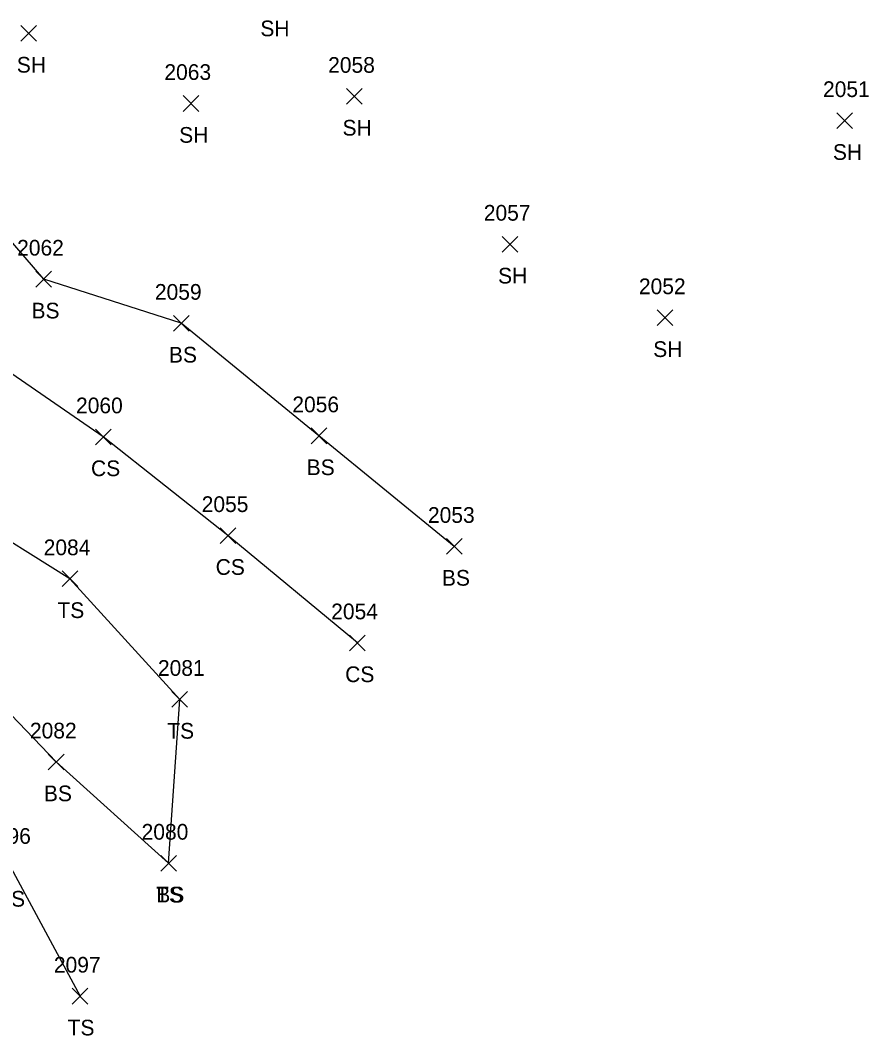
# Model space of a CAD drawing. Extents: x 1520648 to 1523413, y 732854 to 735518.
# Drawn here: x 1522132.5 to 1522240.5, y 733592.7 to 733722 of the extents above; entities that cross this region are included whole.
import ezdxf

# ---------------------------------------------------------------- set-up
doc = ezdxf.new("R2010")
doc.units = 0
for name, color, linetype in [('L_A', 7, 'Continuous'), ('L_I', 7, 'Continuous'), ('L_TIC', 7, 'Continuous'), ('LELB', 7, 'Continuous')]:
    doc.layers.add(name, color=color, linetype=linetype)

msp = doc.modelspace()

# ---------------------------------------------------------------- linework, layer by layer
at = {"layer": 'L_TIC'}
for points in [[(1522132.59, 733719.29), (1522134.59, 733721.29)], [(1522134.59, 733719.29), (1522132.59, 733721.29)], [(1522174.06, 733711.27), (1522176.06, 733713.27)], [(1522176.06, 733711.27), (1522174.06, 733713.27)], [(1522153.26, 733710.36), (1522155.26, 733712.36)], [(1522155.26, 733710.36), (1522153.26, 733712.36)], [(1522236.5, 733708.18), (1522238.5, 733710.18)], [(1522238.5, 733708.18), (1522236.5, 733710.18)], [(1522193.87, 733692.44), (1522195.87, 733694.44)], [(1522195.87, 733692.44), (1522193.87, 733694.44)], [(1522134.51, 733687.99), (1522136.51, 733689.99)], [(1522136.51, 733687.99), (1522134.51, 733689.99)], [(1522213.62, 733683.08), (1522215.62, 733685.08)], [(1522215.62, 733683.08), (1522213.62, 733685.08)], [(1522152.01, 733682.37), (1522154.01, 733684.37)], [(1522154.01, 733682.37), (1522152.01, 733684.37)], [(1522142.09, 733667.91), (1522144.09, 733669.91)], [(1522144.09, 733667.91), (1522142.09, 733669.91)], [(1522169.55, 733668.04), (1522171.55, 733670.04)], [(1522171.55, 733668.04), (1522169.55, 733670.04)], [(1522157.96, 733655.34), (1522159.96, 733657.34)], [(1522159.96, 733655.34), (1522157.96, 733657.34)], [(1522186.77, 733653.96), (1522188.77, 733655.96)], [(1522188.77, 733653.96), (1522186.77, 733655.96)], [(1522137.84, 733649.84), (1522139.84, 733651.84)], [(1522139.84, 733649.84), (1522137.84, 733651.84)], [(1522174.45, 733641.68), (1522176.45, 733643.68)], [(1522176.45, 733641.68), (1522174.45, 733643.68)], [(1522151.83, 733634.48), (1522153.83, 733636.48)], [(1522153.83, 733634.48), (1522151.83, 733636.48)], [(1522136.09, 733626.51), (1522138.09, 733628.51)], [(1522138.09, 733626.51), (1522136.09, 733628.51)], [(1522150.4, 733613.62), (1522152.4, 733615.62)], [(1522152.4, 733613.62), (1522150.4, 733615.62)], [(1522150.4, 733613.62), (1522152.4, 733615.62)], [(1522152.4, 733613.62), (1522150.4, 733615.62)], [(1522139.14, 733596.69), (1522141.14, 733598.69)], [(1522141.14, 733596.69), (1522139.14, 733598.69)]]:
    msp.add_lwpolyline(points, dxfattribs=at)
at = {"layer": 'LELB'}
for points in [[(1522175.45, 733642.68), (1522158.96, 733656.34), (1522143.09, 733668.91), (1522126.49, 733680.32), (1522112.21, 733698.89), (1522093.01, 733716.82), (1522086.71, 733701.67), (1522076.07, 733682.31), (1522062.1, 733669.53), (1522040.49, 733638.5)], [(1522187.77, 733654.96), (1522170.55, 733669.04), (1522153.01, 733683.37), (1522135.51, 733688.99), (1522119.92, 733707.07)], [(1522151.4, 733614.62), (1522152.83, 733635.48), (1522138.84, 733650.84), (1522125.94, 733658.88), (1522109.84, 733673.94), (1522100.92, 733684.14), (1522090.71, 733694.57), (1522087.23, 733686.84), (1522071.15, 733667.54), (1522069.93, 733665.76), (1522040.49, 733638.5)], [(1522151.4, 733614.62), (1522137.09, 733627.51), (1522120.8, 733644.52), (1522115.51, 733655.32), (1522103.6, 733667.72), (1522087.23, 733686.84)], [(1522071.15, 733667.54), (1522091.55, 733646.72), (1522109.98, 733629.81), (1522131.31, 733614.09), (1522140.14, 733597.69)]]:
    msp.add_lwpolyline(points, dxfattribs=at)

# ---------------------------------------------------------------- texts
at = {"layer": 'L_A'}
for s, p in [('SH', (1522163.09, 733719.92)), ('SH', (1522132.08, 733715.29)), ('SH', (1522152.75, 733706.36)), ('SH', (1522173.55, 733707.27)), ('SH', (1522235.99, 733704.18)), ('SH', (1522193.36, 733688.44)), ('BS', (1522133.95, 733683.99)), ('SH', (1522213.11, 733679.08)), ('BS', (1522151.45, 733678.37)), ('CS', (1522141.53, 733663.91)), ('BS', (1522168.99, 733664.04)), ('CS', (1522157.4, 733651.34)), ('BS', (1522186.21, 733649.96)), ('TS', (1522137.25, 733645.84)), ('CS', (1522173.89, 733637.68)), ('TS', (1522151.24, 733630.48)), ('BS', (1522135.53, 733622.51)), ('TS', (1522129.72, 733609.09)), ('TS', (1522149.81, 733609.62)), ('BS', (1522149.84, 733609.62)), ('TS', (1522138.55, 733592.69))]:
    msp.add_text(s, height=2, dxfattribs=at).set_placement(p)
at = {"layer": 'L_I'}
for s, p in [('2058', (1522171.72, 733715.27)), ('2063', (1522150.87, 733714.36)), ('2051', (1522234.73, 733712.18)), ('2057', (1522191.54, 733696.44)), ('2062', (1522132.12, 733691.99)), ('2052', (1522211.29, 733687.08)), ('2059', (1522149.66, 733686.37)), ('2060', (1522139.62, 733671.91)), ('2056', (1522167.16, 733672.04)), ('2055', (1522155.62, 733659.34)), ('2053', (1522184.43, 733657.96)), ('2084', (1522135.5, 733653.84)), ('2054', (1522172.11, 733645.68)), ('2081', (1522150.05, 733638.48)), ('2082', (1522133.75, 733630.51)), ('2096', (1522127.92, 733617.09)), ('2080', (1522147.97, 733617.62)), ('2080', (1522147.97, 733617.62)), ('2097', (1522136.8, 733600.69))]:
    msp.add_text(s, height=2, dxfattribs=at).set_placement(p)

doc.saveas('drawing.dxf')
